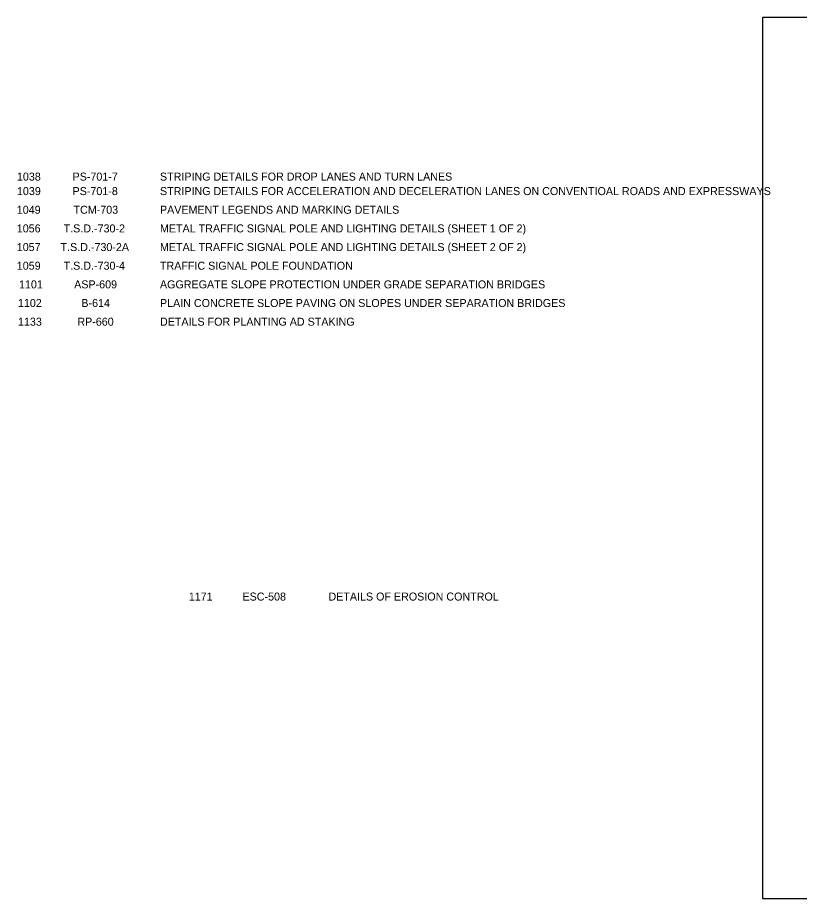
# Model space of a CAD drawing. Extents: x -12822 to 16384, y -6351 to 1913.
# Drawn here: x -1780 to -804, y -4850 to -3750 of the extents above; entities that cross this region are included whole.
import ezdxf

# ---------------------------------------------------------------- set-up
doc = ezdxf.new("R2010")
doc.units = 0
doc.layers.add('Level 10', color=7, linetype='Continuous')
doc.layers.add('Level 62', color=7, linetype='Continuous')

msp = doc.modelspace()

# ---------------------------------------------------------------- linework, layer by layer
at = {"layer": 'Level 62'}
msp.add_lwpolyline([(-850, -4850.3), (850, -4850.3), (850, -3750.3), (-850, -3750.3)], close=True, dxfattribs=at)

# ---------------------------------------------------------------- texts
at = {"layer": 'Level 10'}
for s, p in [('1038', (-1780.5, -3953.9)), ('PS-701-7', (-1711.1, -3953.9)), ('STRIPING DETAILS FOR DROP LANES AND TURN LANES', (-1602, -3953.9)), ('1039', (-1780.5, -3972)), ('PS-701-8', (-1711.1, -3972)), ('STRIPING DETAILS FOR ACCELERATION AND DECELERATION LANES ON CONVENTIOAL ROADS AND EXPRESSWAYS', (-1602, -3972)), ('1049', (-1780.7, -3995.3)), ('TCM-703', (-1709.9, -3995.3)), ('PAVEMENT LEGENDS AND MARKING DETAILS', (-1602, -3995.3)), ('1056', (-1780.7, -4018.6)), ('T.S.D.-730-2', (-1722.2, -4018.6)), ('METAL TRAFFIC SIGNAL POLE AND LIGHTING DETAILS (SHEET 1 OF 2)', (-1602, -4018.6)), ('1057', (-1780.7, -4041.9)), ('T.S.D.-730-2A', (-1726.1, -4041.9)), ('METAL TRAFFIC SIGNAL POLE AND LIGHTING DETAILS (SHEET 2 OF 2)', (-1602, -4041.9)), ('1059', (-1780.7, -4065.2)), ('T.S.D.-730-4', (-1722.2, -4065.2)), ('TRAFFIC SIGNAL POLE FOUNDATION', (-1602, -4065.2)), ('1101', (-1777.9, -4088.5)), ('ASP-609', (-1709.1, -4088.5)), ('AGGREGATE SLOPE PROTECTION UNDER GRADE SEPARATION BRIDGES', (-1602, -4088.5)), ('1102', (-1779.3, -4111.8)), ('B-614', (-1700.1, -4111.8)), ('PLAIN CONCRETE SLOPE PAVING ON SLOPES UNDER SEPARATION BRIDGES', (-1602, -4111.8)), ('1133', (-1779.2, -4135.1)), ('RP-660', (-1705.1, -4135.1)), ('DETAILS FOR PLANTING AD STAKING', (-1602, -4135.1)), ('1171', (-1566, -4478.4)), ('ESC-508', (-1499, -4478.4)), ('DETAILS OF EROSION CONTROL', (-1391.7, -4478.4))]:
    msp.add_text(s, height=10, dxfattribs=at).set_placement(p)

doc.saveas('drawing.dxf')
